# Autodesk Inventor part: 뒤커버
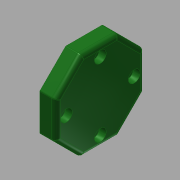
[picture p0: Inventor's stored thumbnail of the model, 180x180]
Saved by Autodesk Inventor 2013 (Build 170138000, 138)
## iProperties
Created: 2015-11
Part Number: 뒤커버
Material: 알루미늄 6061
Document SubType Name: Modeling
Designer: mduedu
Density: 1 g/cm^3
Author: mduedu
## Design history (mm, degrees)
sketch "스케치5" dims "d66" = 60
  geometry: L1 (12.426, 30)-(30, 12.426); L2 (30, 12.426)-(30, -12.426); L3 (30, -12.426)-(12.426, -30); L4 (12.426, -30)-(-12.426, -30); L5 (-12.426, -30)-(-30, -12.426); L6 (-30, -12.426)-(-30, 12.426); L7 (-30, 12.426)-(-12.426, 30); L8 (-12.426, 30)-(12.426, 30); 4 further points
  constraints: 16 end point, 2 coincident, 2 vertical alignment, 1 midpoint, 19 other
extrude "돌출2" new body sketch "스케치5" distance "d67" = 11; taper "d68" = 0 deg
sketch "스케치6"
  geometry: C1 r 16 at (0, 0); 1 further point
  constraints: 1 centre point, 1 coincident
  dimensions: "d69" = 32 diameter of C1
extrude "돌출3" join sketch "스케치6" distance "d70" = 3; taper "d71" = 0 deg
hole "구멍5" diameter "d74" = 25; stored, may be unused: countersink angle "d78" = 90 deg, drill point angle "d80" = 0 deg; dims "d72" = 10, "d73" = 10, "d75" = 6, "d76" = 4, "d77" = 2, "d79" = 10
fillet "모깎기7" dims "d81" = 1
fillet "모깎기8" dims "d82" = 3
fillet "모깎기9" dims "d83" = 3
fillet "모깎기10" dims "d84" = 0.3
sketch "스케치7" dims "d85" = 46
  geometry: 3 further points
  constraints: 2 vertical alignment, 1 coincident, 2 other
hole "구멍6" sketch "스케치7" at (0, 23) diameter "d86" = 4.5; stored, may be unused: countersink angle "d90" = 90 deg, drill point angle "d92" = 0 deg; dims "d87" = 6, "d88" = 8, "d89" = 4.6, "d91" = 10
node "솔리드2"
pattern_circular "원형 패턴3" dims angle "d94" = 360 deg
